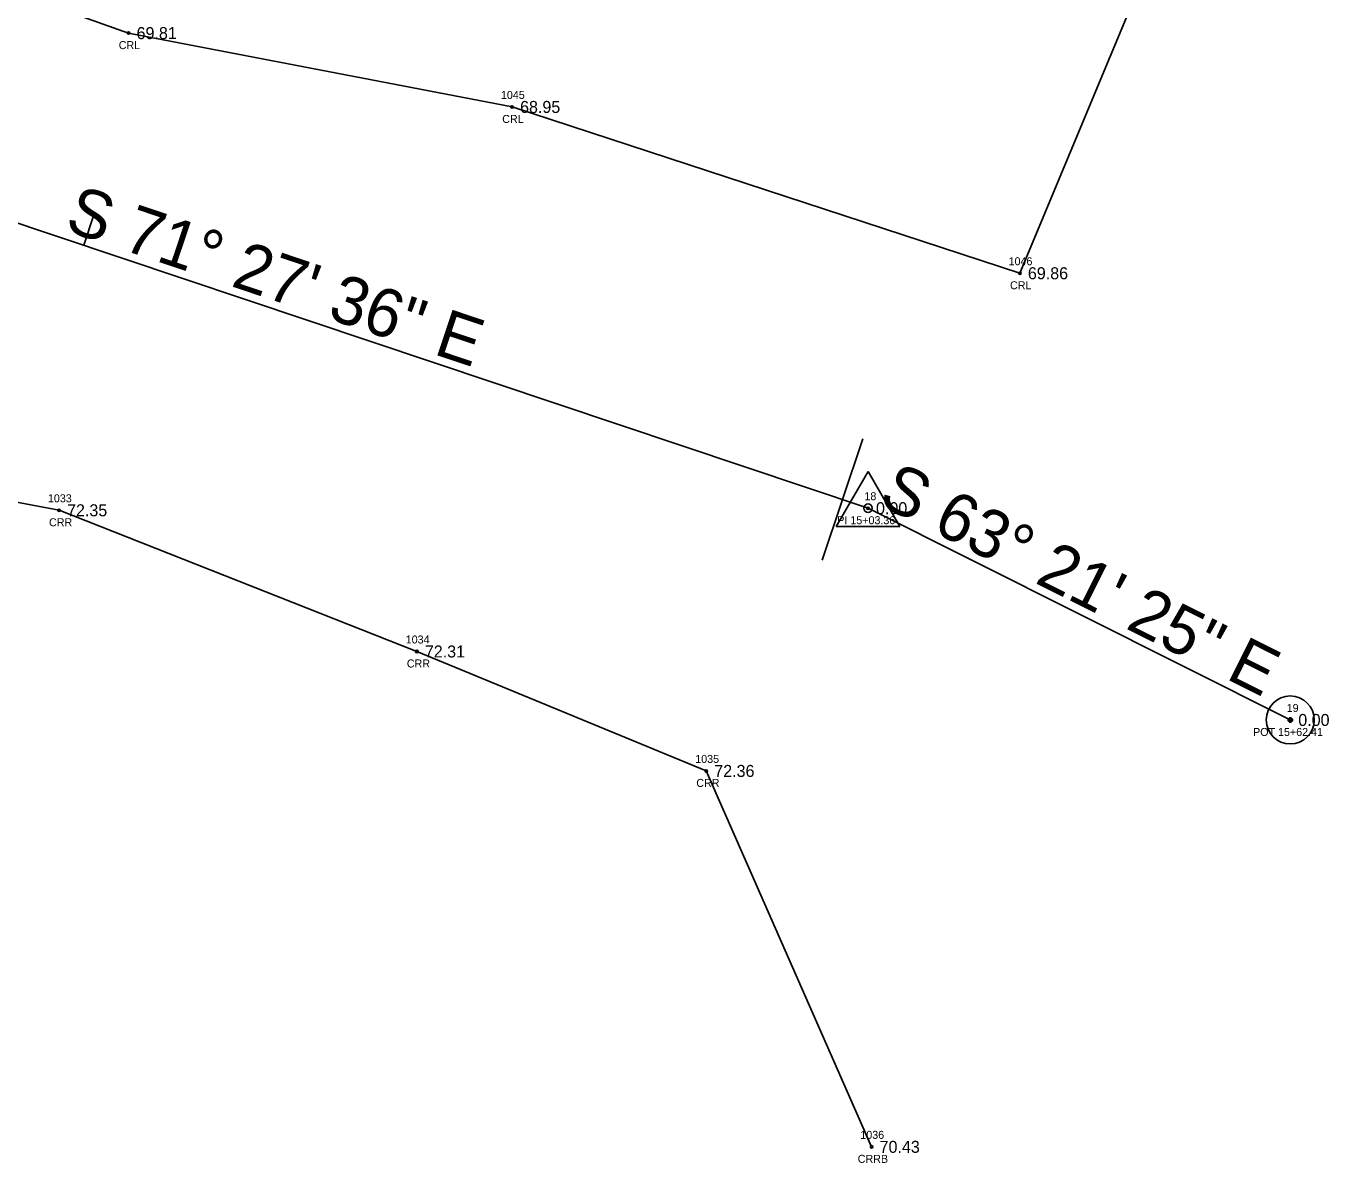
# Model space of a CAD drawing. Extents: x 2505249 to 2506333, y 912937 to 914171.
# Drawn here: x 2505991.3 to 2506154.1, y 913383.5 to 913525.6 of the extents above; entities that cross this region are included whole.
import ezdxf

# ---------------------------------------------------------------- set-up
doc = ezdxf.new("R2010")
doc.units = 0
for name, color, linetype in [('RD_EX_H2O', 7, 'Continuous'), ('RD_EX_H2O_txCode', 7, 'Continuous'), ('RD_EX_TX_H2O_ELEV', 7, 'Continuous'), ('RD_HC_Cl', 7, 'Continuous'), ('RD_HC_Data', 7, 'Continuous'), ('RD_HC_Data_Tic', 7, 'Continuous'), ('RD_HC_Survey_ELEV', 7, 'Continuous'), ('RD_HC_txCode', 7, 'Continuous'), ('RD_SMD_Locator', 7, 'Continuous')]:
    doc.layers.add(name, color=color, linetype=linetype)

msp = doc.modelspace()

# ---------------------------------------------------------------- linework, layer by layer
at = {"layer": 'RD_EX_H2O'}
for points in [[(2505762.26, 913658.11), (2505746.15, 913644.25), (2505726.47, 913615.21), (2505674.21, 913628.01), (2505666.25, 913620.58), (2505714.6, 913592.15), (2505793.9, 913560.45), (2505801.32, 913552.8), (2505803.7, 913539.77), (2505832.63, 913516.96), (2505848.42, 913517.19), (2505881.86, 913528.44), (2505910.2, 913538.78), (2505939.3, 913544.45), (2505946.25, 913542.54), (2505974.65, 913535.18), (2506004.11, 913524.7), (2506052.03, 913515.47), (2506115.49, 913494.68), (2506138.05, 913548.89)], [(2505789.47, 913464.31), (2505795.69, 913463.1), (2505812.13, 913464.37), (2505832.03, 913446.73), (2505876.17, 913453.08), (2505891.76, 913474.03), (2505941.74, 913475.13), (2505995.42, 913465.05), (2506040.13, 913447.4), (2506076.3, 913432.47), (2506096.96, 913385.48)]]:
    msp.add_lwpolyline(points, dxfattribs=at)
at = {"layer": 'RD_HC_Cl'}
for p, q in [((2505947.94, 913515.14), (2506096.51, 913465.31)), ((2506096.51, 913465.31), (2506149.28, 913438.84))]:
    msp.add_line(p, q, dxfattribs=at)
at = {"layer": 'RD_HC_Data'}
for p, q in [((2506092.54, 913463.02), (2506096.51, 913469.9)), ((2506096.51, 913469.9), (2506100.48, 913463.02)), ((2506092.54, 913463.02), (2506100.48, 913463.02))]:
    msp.add_line(p, q, dxfattribs=at)
for centre, radius in [((2506096.51, 913465.31), 0.529), ((2506149.28, 913438.84), 3), ((2506149.28, 913438.84), 0.282)]:
    msp.add_circle(centre, radius, dxfattribs=at)
at = {"layer": 'RD_HC_Data_Tic'}
for p, q in [((2505998.51, 913498.18), (2505999.78, 913501.97)), ((2506093.32, 913466.38), (2506095.86, 913473.97)), ((2506093.32, 913466.38), (2506090.78, 913458.8))]:
    msp.add_line(p, q, dxfattribs=at)
at = {"layer": 'RD_SMD_Locator'}
for centre in [(2506004.11, 913524.7), (2506052.03, 913515.47), (2506115.49, 913494.68), (2505995.42, 913465.05), (2506096.51, 913465.31), (2506040.13, 913447.4), (2506149.28, 913438.84), (2506076.3, 913432.47), (2506096.96, 913385.48)]:
    msp.add_circle(centre, 0.15, dxfattribs=at)

# ---------------------------------------------------------------- texts
at = {"layer": 'RD_EX_H2O_txCode'}
for s, p in [('CRL', (2506002.88, 913522.7)), ('1045', (2506050.64, 913516.47)), ('CRL', (2506050.8, 913513.47)), ('1046', (2506114.08, 913495.68)), ('CRL', (2506114.26, 913492.68)), ('1033', (2505994.03, 913466.05)), ('CRR', (2505994.17, 913463.05)), ('1034', (2506038.74, 913448.4)), ('CRR', (2506038.88, 913445.4)), ('1035', (2506074.92, 913433.47)), ('CRR', (2506075.05, 913430.47)), ('1036', (2506095.55, 913386.48)), ('CRRB', (2506095.23, 913383.48))]:
    msp.add_text(s, height=1, dxfattribs=at).set_placement(p)
at = {"layer": 'RD_EX_TX_H2O_ELEV'}
for s, p in [('69.81', (2506005.11, 913523.95)), ('68.95', (2506053.03, 913514.72)), ('69.86', (2506116.49, 913493.93)), ('72.35', (2505996.42, 913464.3)), ('72.31', (2506041.13, 913446.65)), ('72.36', (2506077.3, 913431.72)), ('70.43', (2506097.96, 913384.73))]:
    msp.add_text(s, height=1.5, dxfattribs=at).set_placement(p)
at = {"layer": 'RD_HC_Data'}
for s, rotation, p in [('S 71%%d 27\' 36" E', 341.46, (2505995.96, 913500.09)), ('S 63%%d 21\' 25" E', 333.357, (2506097.61, 913465.88))]:
    msp.add_text(s, height=6, rotation=rotation, dxfattribs=at).set_placement(p)
at = {"layer": 'RD_HC_Survey_ELEV'}
for p in [(2506097.51, 913464.56), (2506150.28, 913438.09)]:
    msp.add_text('0.00', height=1.5, dxfattribs=at).set_placement(p)
at = {"layer": 'RD_HC_txCode'}
for s, p in [('18', (2506096.06, 913466.31)), ('PI 15+03.36', (2506092.67, 913463.31)), ('19', (2506148.83, 913439.84)), ('POT 15+62.41', (2506144.63, 913436.84))]:
    msp.add_text(s, height=1, dxfattribs=at).set_placement(p)

doc.saveas('drawing.dxf')
